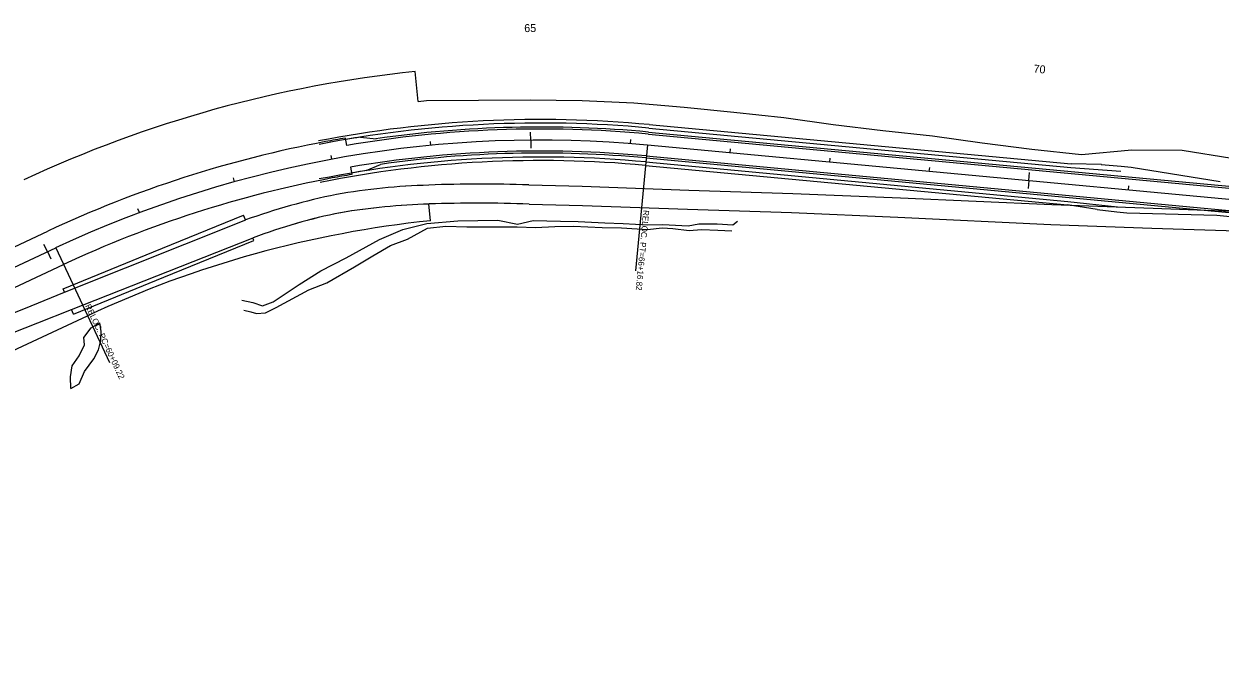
# Model space of a CAD drawing. Extents: x 1965724 to 1970311, y 1117080 to 1118208.
# Drawn here: x 1967654 to 1968850, y 1117457 to 1118099 of the extents above; entities that cross this region are included whole.
import ezdxf

# ---------------------------------------------------------------- set-up
doc = ezdxf.new("R2010")
doc.units = 0
for name, color, linetype in [('RD_EX_H2O_WetLd', 7, 'Continuous'), ('RD_EX_Road', 7, 'Continuous'), ('RD_EX_RW', 7, 'Continuous'), ('RD_HC_CL_Rel', 7, 'Continuous'), ('RD_HC_Data_Rel', 7, 'Continuous'), ('RD_HC_Data_Tic_Rel', 7, 'Continuous'), ('RD_HC_TX_Rel_Sta50', 7, 'Continuous'), ('RD_PD_Bridge', 7, 'Continuous'), ('RD_PD_EarthShd', 7, 'Continuous'), ('RD_PD_Final_TrvlWay', 7, 'Continuous'), ('RD_PD_PaveShd', 7, 'Continuous'), ('RD_PD_RW', 7, 'Continuous'), ('RD_Sketch3', 7, 'Continuous'), ('RD_Sketch4', 7, 'Continuous')]:
    doc.layers.add(name, color=color, linetype=linetype)

msp = doc.modelspace()

# ---------------------------------------------------------------- linework, layer by layer
at = {"layer": 'RD_EX_H2O_WetLd'}
for points in [[(1967871.9, 1117823.2), (1967882.8, 1117820.9), (1967892.5, 1117817.6), (1967903.1, 1117821.5), (1967929.3, 1117838.9), (1967950.7, 1117852.8), (1967976.1, 1117865.5), (1968009.4, 1117883.8), (1968032.7, 1117893.9), (1968056.9, 1117900), (1968088, 1117902.7), (1968127.8, 1117903.4), (1968147.6, 1117899.3), (1968163.2, 1117903), (1968190.6, 1117902.2), (1968208.2, 1117901.8), (1968234.8, 1117900.5), (1968253.3, 1117900.1), (1968277.7, 1117898.7), (1968292.9, 1117899.1), (1968318.2, 1117897.5), (1968328.9, 1117899.6), (1968347.3, 1117899.5), (1968363, 1117898.5), (1968367.5, 1117902.4)], [(1967873.8, 1117813.3), (1967880.7, 1117811.8), (1967886.5, 1117810.1), (1967895.5, 1117810.6), (1967906.3, 1117816.1), (1967938.7, 1117833.6), (1967956.7, 1117840.5), (1967984.4, 1117856.8), (1968002.9, 1117867.5), (1968020.4, 1117877.9), (1968037.5, 1117884.2), (1968057.4, 1117895.2), (1968076, 1117897.2), (1968097, 1117896.5), (1968127.6, 1117896.5), (1968147.3, 1117896.5), (1968165.5, 1117895.9), (1968184.9, 1117896.8), (1968203.6, 1117897.4), (1968232.3, 1117895.9), (1968251.4, 1117895.6), (1968277.5, 1117893.8), (1968292.3, 1117895.6), (1968302.8, 1117895.1), (1968319.2, 1117892.9), (1968331.6, 1117894.1), (1968347.7, 1117893.2), (1968362, 1117892.5)], [(1967700.8, 1117735), (1967700.5, 1117746.7), (1967702.2, 1117757.8), (1967709.3, 1117767.5), (1967714.4, 1117778.7), (1967714, 1117786), (1967721.2, 1117795.5), (1967729.7, 1117800.6)], [(1967700.8, 1117735), (1967709.1, 1117739.5), (1967714.5, 1117752), (1967723.9, 1117764.7), (1967728.5, 1117773.7), (1967731, 1117782.9), (1967731.1, 1117791.9), (1967729.7, 1117800.6)]]:
    msp.add_lwpolyline(points, dxfattribs=at)
at = {"layer": 'RD_EX_Road'}
for p, q in [((1967694.4, 1117831.2), (1967875.7, 1117903.5)), ((1967701.6, 1117814), (1967883.1, 1117885.6))]:
    msp.add_line(p, q, dxfattribs=at)
for points in [[(1968158.7, 1117938.6), (1968212.1, 1117937.2), (1968318.8, 1117933.3), (1968422.8, 1117929.9), (1968530.5, 1117925.7)], [(1968530.5, 1117925.7), (1968682, 1117919), (1968783.2, 1117915.4), (1968888.6, 1117911.4), (1968991.2, 1117907.1), (1969092, 1117903.1), (1969191.1, 1117898.7), (1969283.3, 1117895.4)], [(1968159.2, 1117919.4), (1968212.5, 1117918), (1968317.5, 1117914.4), (1968421.5, 1117910.8), (1968527.8, 1117906.4)], [(1968527.8, 1117906.4), (1968680.8, 1117899.1), (1968781.7, 1117895.4), (1968887.9, 1117891.8), (1968988.7, 1117888.2), (1969090.1, 1117882.8), (1969189.3, 1117879), (1969282.9, 1117875.4)], [(1966769.5, 1117457.5), (1966870.2, 1117497.3), (1966971.2, 1117539), (1967071.1, 1117580.2), (1967172.6, 1117621.5), (1967270.8, 1117661.7), (1967321.1, 1117682.6), (1967371.5, 1117702.9), (1967470.3, 1117741.6), (1967566.7, 1117779.5), (1967661.2, 1117817.5), (1967694.4, 1117831.2)], [(1967302.2, 1117654.1), (1967379.3, 1117686.2), (1967476.1, 1117724.4), (1967573.9, 1117763.5), (1967667.7, 1117800.7), (1967701.6, 1117814)]]:
    msp.add_lwpolyline(points, dxfattribs=at)
for centre, radius, start, end in [((1968075.1, 1117320.6), 617.9, 91.4965, 100.1295), ((1968111.4, 1116608.6), 1330.8, 87.9632, 92.259), ((1968104.9, 1117261.1), 682.1, 101.7162, 109.6396), ((1968080.7, 1117246.5), 673.3, 91.837, 99.4057), ((1968107.6, 1116504.3), 1416, 87.9115, 91.9598), ((1968080.6, 1117363), 558.7, 101.3479, 110.7006)]:
    msp.add_arc(centre, radius, start, end, dxfattribs=at)
at = {"layer": 'RD_EX_RW'}
for p, q in [((1967783.4, 1117871.6), (1967873.6, 1117908.4)), ((1967875.6, 1117903.5), (1967873.6, 1117908.4)), ((1967793.7, 1117846.2), (1967884, 1117883.1)), ((1967884, 1117883.1), (1967883, 1117885.6)), ((1967693.2, 1117834.7), (1967783.4, 1117871.6)), ((1967703.5, 1117809.4), (1967793.7, 1117846.2)), ((1967694.6, 1117831.3), (1967693.2, 1117834.7)), ((1967703.5, 1117809.4), (1967701.6, 1117814))]:
    msp.add_line(p, q, dxfattribs=at)
for points in [[(1968059, 1117938.4), (1968058.9, 1117938.4), (1968058.9, 1117938.4)], [(1968158.7, 1117938.6), (1968212.1, 1117937.2), (1968318.8, 1117933.3), (1968422.8, 1117929.9), (1968530.5, 1117925.7)], [(1968530.5, 1117925.7), (1968682, 1117919), (1968783.2, 1117915.4), (1968888.6, 1117911.4), (1968991.2, 1117907.1), (1969092, 1117903.1), (1969191.1, 1117898.7), (1969283.3, 1117895.4)], [(1968159.2, 1117919.4), (1968212.5, 1117918), (1968317.5, 1117914.4), (1968421.5, 1117910.8), (1968527.8, 1117906.4)], [(1967970.6, 1117910.8), (1967970.7, 1117910.8), (1967970.8, 1117910.8)], [(1968527.8, 1117906.4), (1968680.8, 1117899.1), (1968781.7, 1117895.4), (1968887.9, 1117891.8), (1968988.7, 1117888.2), (1969090.1, 1117882.8), (1969189.3, 1117879), (1969282.9, 1117875.4)], [(1966769.5, 1117457.5), (1966870.2, 1117497.3), (1966971.2, 1117539), (1967071.1, 1117580.2), (1967172.6, 1117621.5), (1967270.8, 1117661.7), (1967321.1, 1117682.6), (1967371.5, 1117702.9), (1967470.3, 1117741.6), (1967566.7, 1117779.5), (1967661.2, 1117817.5), (1967694.6, 1117831.3)], [(1967302.2, 1117654.1), (1967379.3, 1117686.2), (1967476.1, 1117724.4), (1967573.9, 1117763.5), (1967667.7, 1117800.7), (1967701.6, 1117814)]]:
    msp.add_lwpolyline(points, dxfattribs=at)
for centre, radius, start, end in [((1968075.1, 1117320.6), 617.9, 91.4996, 100.1295), ((1968111.4, 1116608.6), 1330.8, 87.9632, 92.2576), ((1968104.9, 1117261.1), 682.1, 101.7162, 109.6396), ((1968080.7, 1117246.5), 673.3, 91.837, 99.3984), ((1968107.6, 1116504.3), 1416, 87.9115, 91.9598), ((1968080.6, 1117363), 558.7, 101.3567, 110.7006)]:
    msp.add_arc(centre, radius, start, end, dxfattribs=at)
at = {"layer": 'RD_HC_CL_Rel'}
for p, q in [((1968277.4, 1117978.5), (1969226.4, 1117889.9)), ((1966858.9, 1117489.3), (1967685.7, 1117875.7))]:
    msp.add_line(p, q, dxfattribs=at)
msp.add_arc((1968170.8, 1116837.5), 1145.9, 84.6661, 115.0463, dxfattribs=at)
at = {"layer": 'RD_HC_Data_Rel'}
for p, q in [((1968277.4, 1117978.5), (1968265.6, 1117852.6)), ((1967685.7, 1117875.7), (1967739.4, 1117760.9))]:
    msp.add_line(p, q, dxfattribs=at)
at = {"layer": 'RD_HC_Data_Tic_Rel'}
for p, q in [((1968160.7, 1117983.4), (1968160.6, 1117991.4)), ((1968160.7, 1117983.4), (1968160.8, 1117975.4)), ((1968260.6, 1117979.9), (1968260.9, 1117983.9)), ((1968060.9, 1117978.1), (1968060.5, 1117982.1)), ((1968360.2, 1117970.7), (1968360.5, 1117974.7)), ((1967961.9, 1117964.2), (1967961.1, 1117968.1)), ((1968459.7, 1117961.4), (1968460.1, 1117965.4)), ((1968559.3, 1117952.1), (1968559.7, 1117956.1)), ((1968658.9, 1117942.8), (1968659.6, 1117950.8)), ((1967864.5, 1117941.7), (1967863.4, 1117945.6)), ((1968658.9, 1117942.8), (1968658.1, 1117934.9)), ((1968758.4, 1117933.5), (1968758.8, 1117937.5)), ((1967769.4, 1117910.8), (1967768, 1117914.6)), ((1967677.4, 1117871.8), (1967674, 1117879)), ((1967677.4, 1117871.8), (1967680.7, 1117864.5))]:
    msp.add_line(p, q, dxfattribs=at)
at = {"layer": 'RD_PD_Bridge'}
for p, q in [((1967576.2, 1117844.9), (1967677.9, 1117892.4)), ((1967591.9, 1117811.4), (1967693.5, 1117858.9))]:
    msp.add_line(p, q, dxfattribs=at)
for radius in [1164.4, 1127.4]:
    msp.add_arc((1968170.8, 1116837.5), radius, 100.6572, 115.0463, dxfattribs=at)
at = {"layer": 'RD_PD_EarthShd'}
for p, q in [((1968279.3, 1117998.9), (1968701.2, 1117959.5)), ((1968731.4, 1117958.8), (1968701.3, 1117959.5)), ((1968275.4, 1117958.1), (1968697.4, 1117918.7)), ((1968731.3, 1117958.8), (1968751.3, 1117957.3)), ((1968751.2, 1117957.3), (1968761.2, 1117956.4)), ((1968761.2, 1117956.4), (1968850.1, 1117942.1)), ((1968727.2, 1117913.8), (1968697.5, 1117918.6)), ((1968727.1, 1117913.8), (1968747, 1117911.5)), ((1968747, 1117911.5), (1968756.9, 1117910.6)), ((1968756.9, 1117910.6), (1968846.9, 1117908.2)), ((1968846.9, 1117908.2), (1969224.9, 1117872.9))]:
    msp.add_line(p, q, dxfattribs=at)
for radius, end in [(1166.4, 100.9918), (1125.4, 101.2973)]:
    msp.add_arc((1968170.8, 1116837.5), radius, 84.6661, end, dxfattribs=at)
at = {"layer": 'RD_PD_Final_TrvlWay'}
for p, q in [((1967976.8, 1117978), (1967975.5, 1117985.4)), ((1968278.4, 1117989.4), (1969227.5, 1117900.8)), ((1968276.3, 1117967.5), (1969225.4, 1117878.9)), ((1967980.4, 1117956.3), (1967981.7, 1117949))]:
    msp.add_line(p, q, dxfattribs=at)
for radius, start, end in [(1164.4, 99.6572, 100.6572), (1156.9, 84.6661, 99.6572), (1134.9, 84.6661, 99.6572), (1127.4, 99.6572, 100.6572)]:
    msp.add_arc((1968170.8, 1116837.5), radius, start, end, dxfattribs=at)
at = {"layer": 'RD_PD_PaveShd'}
for p, q in [((1967990.5, 1117986.4), (1968006.1, 1117984.7)), ((1968278.6, 1117991.4), (1969227.6, 1117902.8)), ((1968276.1, 1117965.5), (1969225.2, 1117876.9)), ((1967996.3, 1117952.9), (1968010.4, 1117959))]:
    msp.add_line(p, q, dxfattribs=at)
for radius, start, end in [(1158.9, 84.6661, 98.1741), (1162.9, 98.9192, 99.6572), (1132.9, 84.6661, 98.14), (1128.9, 98.8949, 99.6572)]:
    msp.add_arc((1968170.8, 1116837.5), radius, start, end, dxfattribs=at)
at = {"layer": 'RD_PD_RW'}
for p, q in [((1968048.3, 1118022.1), (1968045.2, 1118051.9)), ((1968048.3, 1118022.1), (1968056.6, 1118022.8)), ((1968056.6, 1118022.8), (1968108.6, 1118023.3)), ((1968108.6, 1118023.3), (1968160.3, 1118023.6)), ((1968160.3, 1118023.6), (1968212.1, 1118023)), ((1968212.1, 1118023), (1968263.8, 1118020.6)), ((1968263.8, 1118020.6), (1968314.2, 1118016.3)), ((1968314.2, 1118016.3), (1968364, 1118011.2)), ((1968364, 1118011.2), (1968413.7, 1118005.8)), ((1968413.7, 1118005.8), (1968463.3, 1117999.1)), ((1968463.3, 1117999.1), (1968512.9, 1117993.1)), ((1968512.9, 1117993.1), (1968562.6, 1117987.5)), ((1968562.6, 1117987.5), (1968612.2, 1117980.7)), ((1968612.2, 1117980.7), (1968661.8, 1117974.4)), ((1968661.8, 1117974.4), (1968711.4, 1117968.9)), ((1968711.4, 1117968.9), (1968762, 1117973.5)), ((1968762, 1117973.5), (1968812.3, 1117973.2)), ((1968812.3, 1117973.2), (1968861.9, 1117965.3)), ((1968060.6, 1117902.7), (1968058.9, 1117919.5)), ((1967529.7, 1117720), (1967717.5, 1117807.7))]:
    msp.add_line(p, q, dxfattribs=at)
for radius in [1220.9, 1070.9]:
    msp.add_arc((1968170.8, 1116837.5), radius, 95.9072, 115.0463, dxfattribs=at)
at = {"layer": 'RD_Sketch3'}
for p, q in [((1968275.8, 1117961.5), (1968697.7, 1117922.1)), ((1968697.8, 1117922.1), (1968747.4, 1117916.5))]:
    msp.add_line(p, q, dxfattribs=at)
msp.add_arc((1968170.8, 1116837.5), 1128.9, 84.6661, 101.3137, dxfattribs=at)
at = {"layer": 'RD_Sketch4'}
for p, q in [((1968278.9, 1117995.4), (1968700.9, 1117956)), ((1968700.9, 1117956), (1968750.8, 1117952.3))]:
    msp.add_line(p, q, dxfattribs=at)
msp.add_arc((1968170.8, 1116837.5), 1162.9, 84.6661, 100.9906, dxfattribs=at)

# ---------------------------------------------------------------- texts
at = {"layer": 'RD_HC_Data_Rel'}
for s, rotation, p in [('RELOC. PT=66+16.82', 264.6661, (1968273.3, 1117913.6)), ('RELOC. PC=60+09.22', 295.0463, (1967715, 1117817.6))]:
    msp.add_text(s, height=6, rotation=rotation, dxfattribs=at).set_placement(p)
at = {"layer": 'RD_HC_TX_Rel_Sta50'}
for s, rotation, p in [('65', 0.5072, (1968154.3, 1118091.3)), ('70', 354.6661, (1968663.3, 1118050.9))]:
    msp.add_text(s, height=8, rotation=rotation, dxfattribs=at).set_placement(p)

doc.saveas('drawing.dxf')
